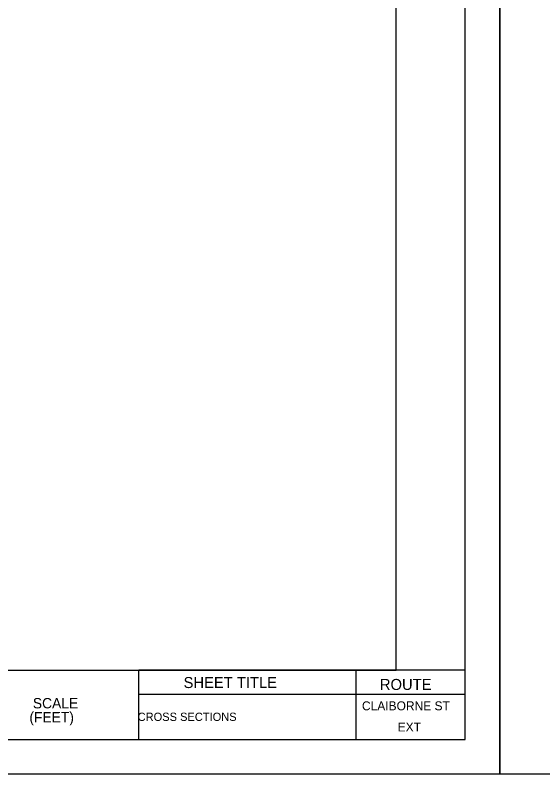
# Model space of a CAD drawing. Extents: x 1797478 to 1803816, y 246529 to 250952.
# Drawn here: x 1802385.7 to 1802462.3, y 250064.4 to 250174.4 of the extents above; entities that cross this region are included whole.
import ezdxf

# ---------------------------------------------------------------- set-up
doc = ezdxf.new("R2010")
doc.units = 0
for name, color, linetype in [('ANNO-SHT', 7, 'Continuous'), ('ANNO-SYMB', 7, 'Continuous'), ('ANNO-TXT', 7, 'Continuous'), ('Level 6', 7, 'Continuous'), ('Level 62', 7, 'Continuous'), ('SHT-BDR', 7, 'Continuous'), ('SHT-BNDRY', 7, 'Continuous')]:
    doc.layers.add(name, color=color, linetype=linetype)

msp = doc.modelspace()

# ---------------------------------------------------------------- linework, layer by layer
at = {"layer": 'ANNO-TXT'}
for p, q in [((1802403.66, 250075.96), (1802435.19, 250075.96)), ((1802435.19, 250075.96), (1802451, 250075.96))]:
    msp.add_line(p, q, dxfattribs=at)
at = {"layer": 'Level 6'}
msp.add_line((1802451, 250079.43), (1802403.66, 250079.43), dxfattribs=at)
at = {"layer": 'Level 62'}
for points in [[(1802116, 250064.42), (1802456, 250064.42), (1802456, 250284.42), (1802116, 250284.42)], [(1802456, 250064.42), (1802796, 250064.42), (1802796, 250284.42), (1802456, 250284.42)]]:
    msp.add_lwpolyline(points, close=True, dxfattribs=at)
at = {"layer": 'SHT-BDR'}
msp.add_lwpolyline([(1802141, 250079.43), (1802441, 250079.43), (1802441, 250269.43), (1802141, 250269.43)], close=True, dxfattribs=at)
at = {"layer": 'SHT-BNDRY'}
for p, q in [((1802403.66, 250069.42), (1802403.66, 250079.43)), ((1802435.19, 250069.42), (1802435.19, 250079.43))]:
    msp.add_line(p, q, dxfattribs=at)
msp.add_lwpolyline([(1802128.5, 250069.42), (1802451, 250069.42), (1802451, 250279.42), (1802128.5, 250279.42)], close=True, dxfattribs=at)

# ---------------------------------------------------------------- texts
at = {"layer": 'ANNO-SHT'}
for s, height, p in [('CLAIBORNE ST', 1.3, (1802436.02, 250073.63)), ('          CROSS SECTIONS          ', 1.2, (1802399.03, 250072.09)), ('EXT', 1.3, (1802441.2, 250070.56))]:
    msp.add_text(s, height=height, rotation=360, dxfattribs=at).set_placement(p)
at = {"layer": 'ANNO-SYMB'}
for s, p in [('SCALE', (1802388.29, 250073.91)), ('(FEET)', (1802387.79, 250071.88))]:
    msp.add_text(s, height=1.499, rotation=0.0572, dxfattribs=at).set_placement(p)
at = {"layer": 'ANNO-TXT'}
for s, p in [('SHEET TITLE', (1802410.15, 250076.86)), ('ROUTE', (1802438.62, 250076.58))]:
    msp.add_text(s, height=1.6, dxfattribs=at).set_placement(p)

doc.saveas('drawing.dxf')
